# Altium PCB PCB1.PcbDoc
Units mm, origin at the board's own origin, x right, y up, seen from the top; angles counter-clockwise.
Board outline 84.11 x 84.11 mm, 2 copper layers (Top Layer, Bottom Layer); 12 components, 15 nets, 50 pads, 0 vias.
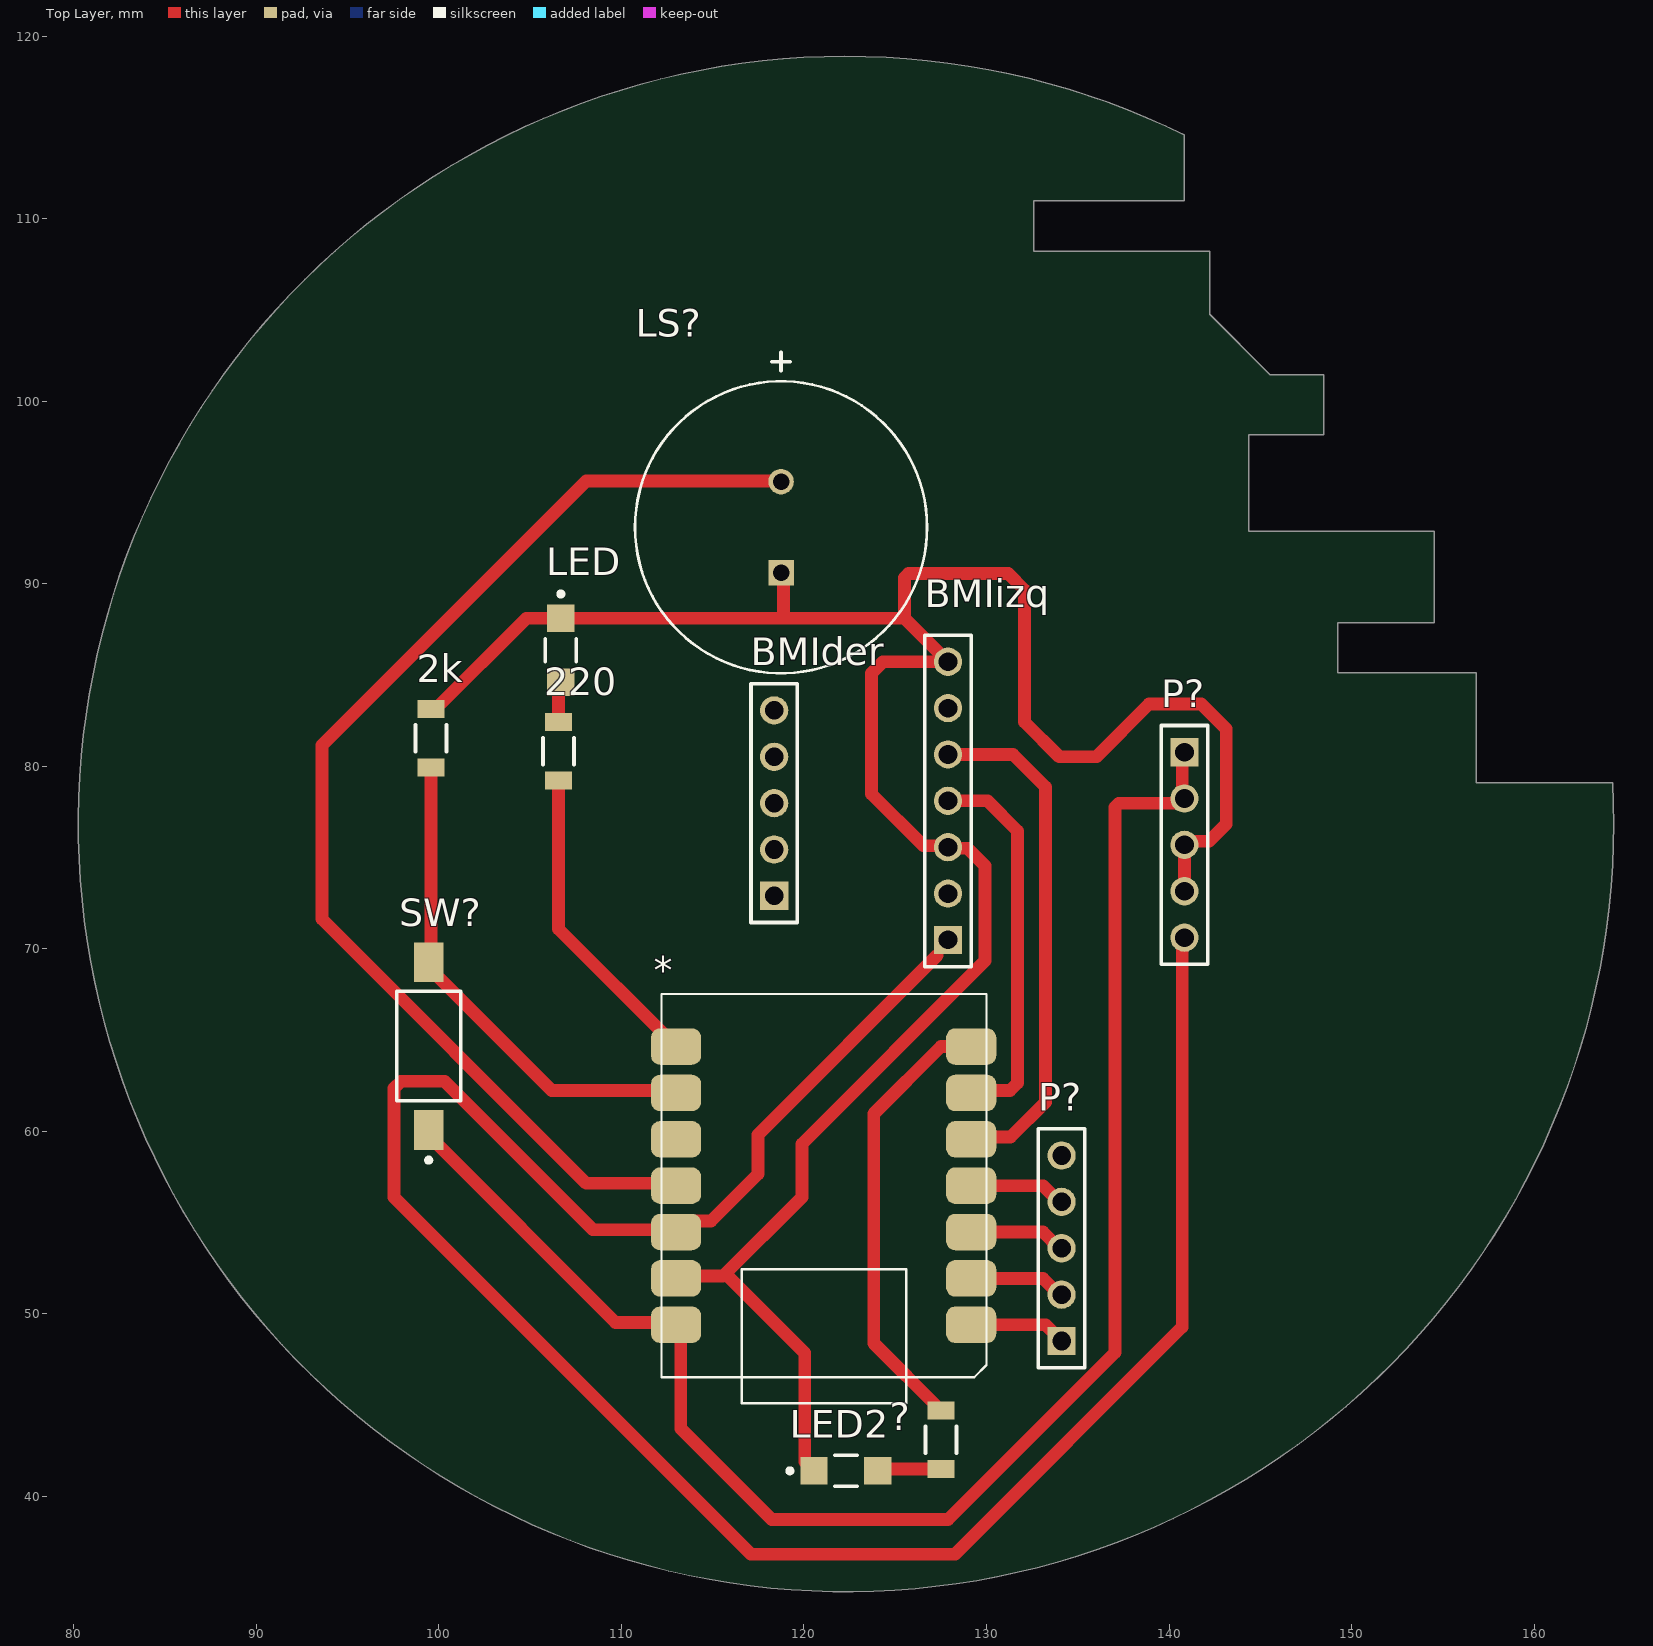
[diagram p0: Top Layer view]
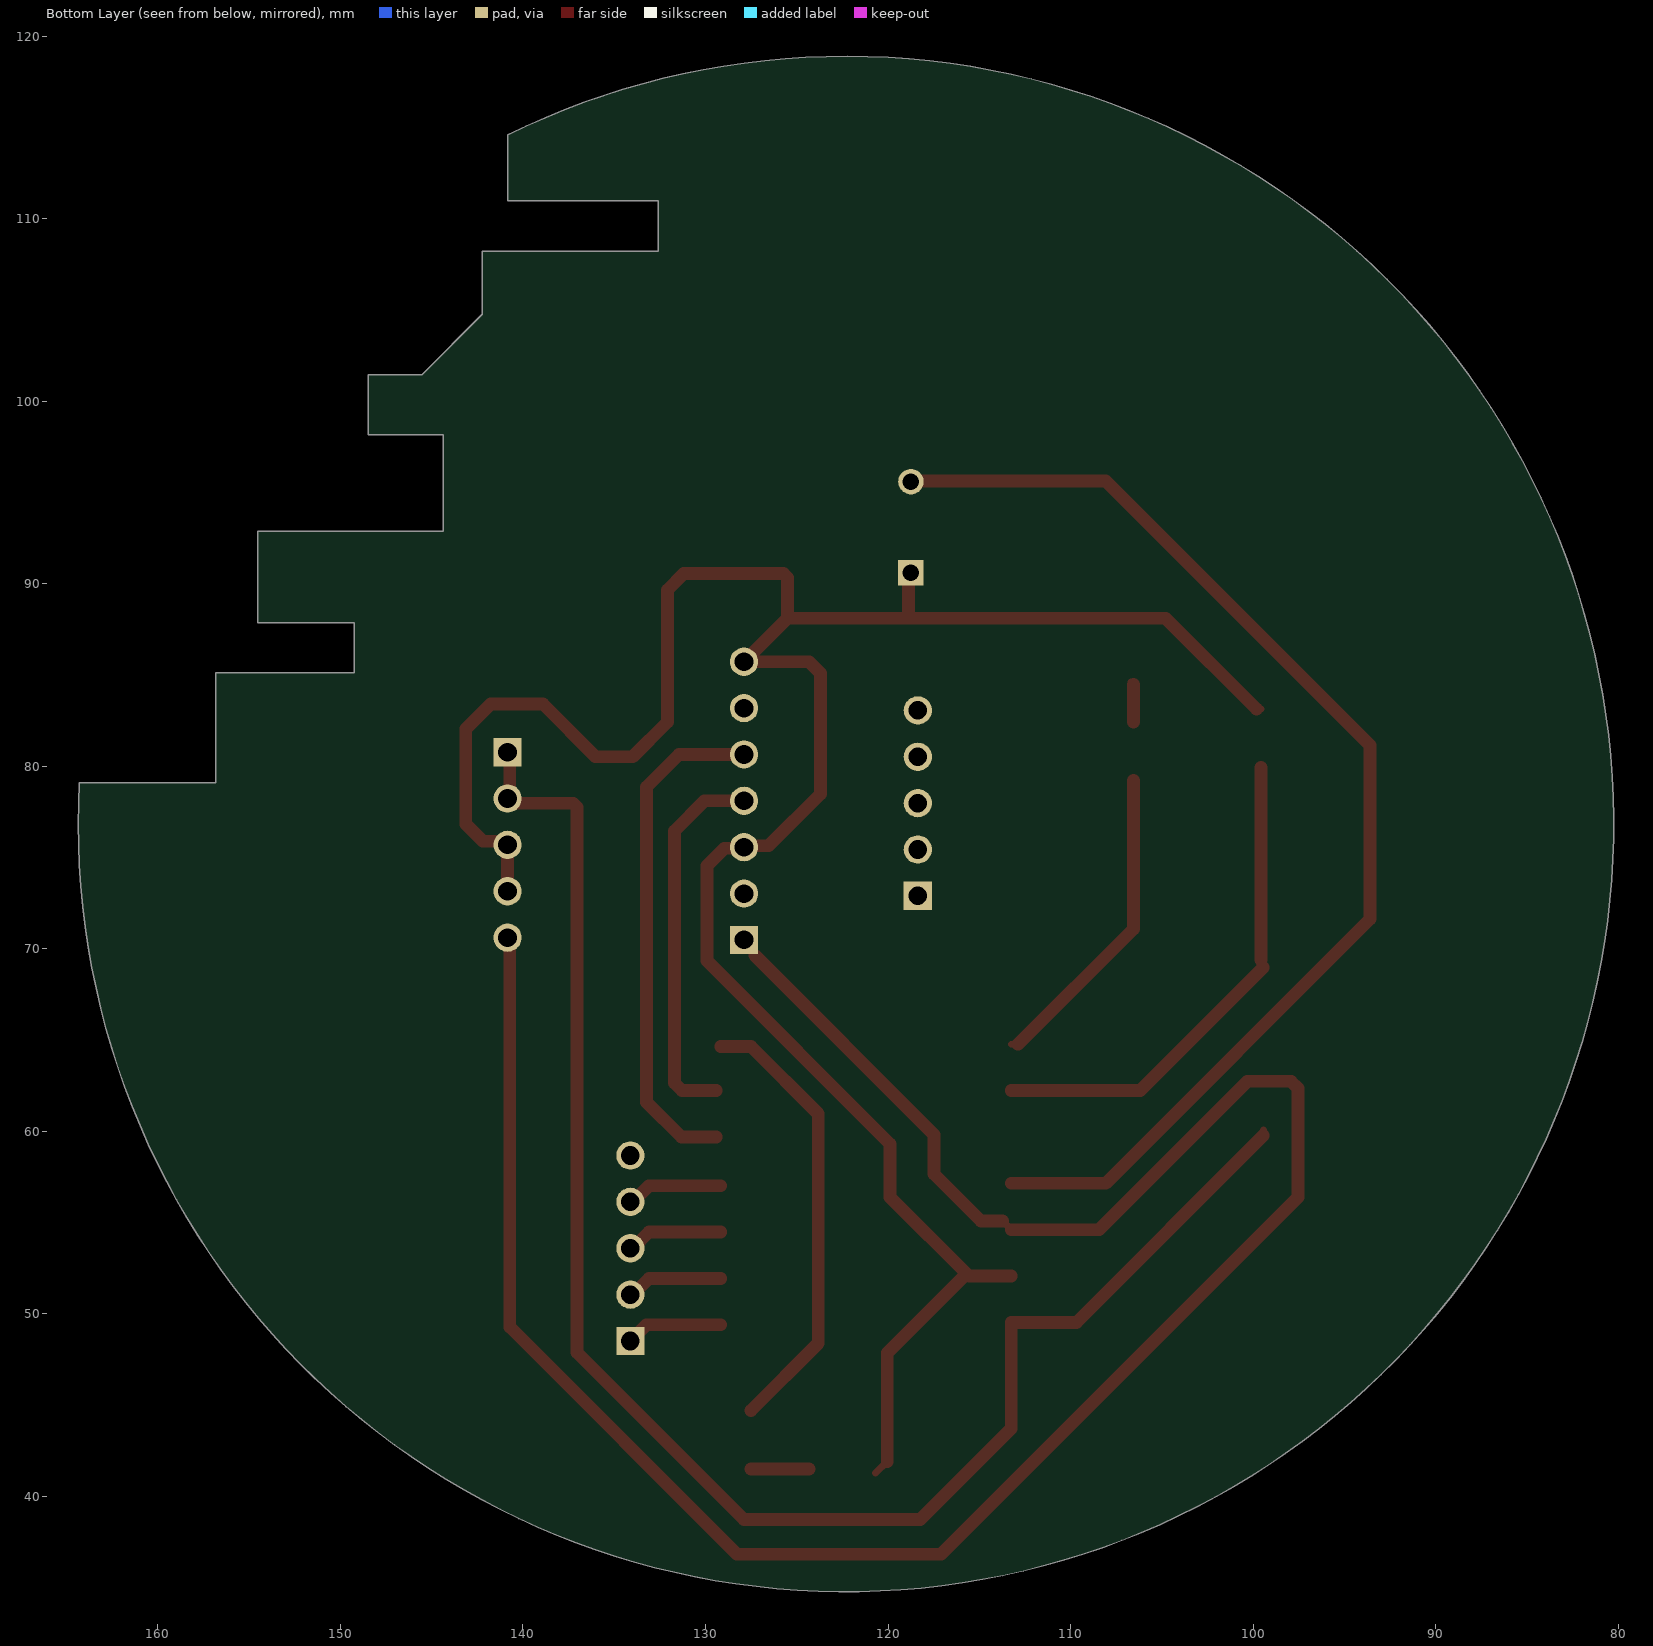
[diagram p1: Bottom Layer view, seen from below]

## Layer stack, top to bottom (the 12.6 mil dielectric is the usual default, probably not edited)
Top Solder: solder mask 0.0102, Solder Resist, Dk 3.5
Top Layer: signal copper 0.0356
Dielectric 1: dielectric 0.32, FR-4, Dk 4.8
Bottom Layer: signal copper 0.0356
Bottom Solder: solder mask 0.0102, Solder Resist, Dk 3.5

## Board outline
144.376,98.148 148.486,98.148 148.486,101.45 145.537,101.45 142.226,104.761 142.226,108.218 132.574,108.218 132.574,110.984 140.829,110.984 140.829,114.59 ccw(c122.301,76.835) 164.296,79.098 156.822,79.098 156.822,85.113 149.248,85.113 149.248,87.861 154.536,87.861 154.536,92.86 144.376,92.86

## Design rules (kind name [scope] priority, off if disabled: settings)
Clearance [All] p1: gap=0.254 ignorepadtopadclearanceinfootprint=FALSE
PolygonConnect [All] p1: connectstyle=Relief reliefconductorwidth=0.254 reliefentries=4 polygonreliefangle="90 Angle" airgapwidth=0.254
RoutingVias [All] p1: holewidth=0.711 width=1.27 viastyle="Through Hole" minholewidth=0.711 minwidth=1.27 maxholewidth=0.711 maxwidth=1.27
SolderMaskExpansion [All] p1: expansion=0.102 istentingtop=FALSE
SupplyNets "Schematic Supply Nets_1" [InNet('GND')] p1: voltage=0.000
SupplyNets "Schematic Supply Nets" [InNet('VCC')] p2: voltage=0.000
Width [OnLayer('Mechanical 1')] p1: maxlimit=0.7 minlimit=0.7 preferedwidth=0.7 minimp=50.000000 maximp=50.000000 favimp=50.000000
30 further rules are at their usual default settings.

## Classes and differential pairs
component class Sheet1: 2k 220 * ? BMIder BMIizq LED LED2 LS? P? SW?

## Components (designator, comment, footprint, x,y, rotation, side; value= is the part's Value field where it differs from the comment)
2k "RC1206JR-070RL" FP-RC1206-MFG 99.568,81.534 r270 top value=0Ω
220 "RC1206JR-070RL" FP-RC1206-MFG 106.553,80.823 r90 top value=0Ω
* "XIAO ESP32C3" MOUDLE14P-SMD-2.54-21X17.8MM 129.994,67.523 r180 top value=MOUDLE-SEEEDUINO-XIAO-ESP32C3
? "RC1206JR-070RL" FP-RC1206-MFG 127.508,43.104 r270 top value=0Ω
BMIder "TSW-105-05-L-S" SMTC-TSW-105-05-X-S 118.364,72.898 r90 top
BMIizq "TSW-107-05-G-S" SMTC-TSW-107-05-X-S 127.889,70.485 r90 top
LED "LTST-C150AKT" FP-LTST-C150AKT-MFG 106.68,86.36 r270 top
LED2 "LTST-C150AKT" FP-LTST-C150AKT-MFG 122.301,41.402 r0 top
LS? "SD1614T5-A1" FP-SD1614T5-A1-MFG 118.745,93.091 r90 top
P? "TSW-105-05-L-S" SMTC-TSW-105-05-X-S 134.112,48.514 r90 top
P? "TSW-105-05-L-S" SMTC-TSW-105-05-X-S 140.843,80.772 r270 top
SW? "FSMSMTR" TECO-FSMSMTR_V 99.441,64.666 r90 top

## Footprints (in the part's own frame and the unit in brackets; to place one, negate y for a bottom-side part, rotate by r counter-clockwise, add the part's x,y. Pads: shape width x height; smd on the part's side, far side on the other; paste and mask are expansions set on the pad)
FP-LTST-C150AKT-MFG [mm]
  rect 1.5x1.5 smd paste+0 mask+0: 1(-1.75,0) 2(1.75,0)
  silkscreen extent -3.2,-0.85 0.63,0.85, body extent -2.6,-0.95 2.6,0.95, height 0.25
FP-RC1206-MFG [mm]
  rect 1x1.5 smd paste+0 mask+0: 1(-1.6,0) 2(1.6,0)
  silkscreen extent -0.72,-0.85 0.72,0.85, body extent -2.2,-0.95 2.2,0.95, height 0.25
FP-SD1614T5-A1-MFG [mm]
  rect 1.4x1.4 hole 0.9 paste-2539.97 mask+0: 1(-2.5,0)
  round 1.4 hole 0.9 paste-2539.97 mask+0: 2(2.5,0)
  silkscreen extent -8,-8 9.57,8, body extent -8.1,-8.1 8.1,8.1, height 0.25
MOUDLE14P-SMD-2.54-21X17.8MM [mm]
  rrect50% 2.75x2 smd: 1(0.835,18.12) 2(0.835,15.58) 3(0.835,13.04) 4(0.835,10.5) 5(0.835,7.96) 6(0.835,5.42) 7(0.835,2.88) 8(17,2.88) 9(17,5.42) 10(17,7.96) 11(17,10.5) 12(17,13.04) 13(17,15.58) 14(17,18.12)
  silkscreen extent 0,0 17.8,22.42, body extent 0,0 17.78,22.46, height 4.19
SMTC-TSW-105-05-X-S [mm] ".025 SQ Post Terminal Strip Assembly, 1x5 Pins, Vertical, 2.54mm Pitch, Male"
  rect 1.55x1.55 hole 1.02: 1(0,0)
  round 1.55 hole 1.02: 2(2.54,0) 3(5.08,0) 4(7.62,0) 5(10.16,0)
  silkscreen extent -1.46,-1.27 11.62,1.27, body extent -1.27,-1.27 11.43,1.27, height 5.21
SMTC-TSW-107-05-X-S [mm] ".025 SQ Post Terminal Strip Assembly, 1x7 Pins, Vertical, 2.54mm Pitch, Male"
  rect 1.55x1.55 hole 1.02: 1(0,0)
  round 1.55 hole 1.02: 2(2.54,0) 3(5.08,0) 4(7.62,0) 5(10.16,0) 6(12.7,0) 7(15.24,0)
  silkscreen extent -1.46,-1.27 16.7,1.27, body extent -1.27,-1.27 16.51,1.27, height 5.21
TECO-FSMSMTR_V [mm] "SMD, 2-Leads, Body 6x3.5mm, Pitch 9.19mm"
  rect 2.2x1.6 smd: 1(-4.595,0)
  rect 2.18x1.6 smd: 2(4.595,0)
  silkscreen extent -6.37,-1.75 3,1.75, body extent -4.98,-1.75 4.98,1.75, height 4.4

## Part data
2k 220 ?: library part CMP-2100-03681-2, "RES SMD 0 OHM JUMPER 1/4W 1206", Manufacturer=YAGEO, Package=RC1206, Power Rating=0.25W, Resistance=0Ω, Temperature="-55°C to +155°C", Temperature Coefficient=300ppm/°C, Temperature Range High=+155°C, Temperature Range Low=-55°C, Tolerance=5%, Voltage Rating=200V
*: library part MOUDLE-SEEEDUINO-XIAO-ESP32C3
BMIder P? P?: library part CMP-1024-00366-1, "0.025\" SQ Post Header, Through-hole, Vertical, -55 to 125 degC, 2.54 mm Pitch, 5-Pin, Male, RoHS", Manufacturer=Samtec, Temperature Range="-55 to 125 degC"
BMIizq: library part CMP-1024-00400-1, "0.025\" SQ Post Header, Through-hole, Vertical, -55 to 125 degC, 2.54 mm Pitch, 7-Pin, Male, RoHS", Manufacturer=Samtec, Temperature Range="-55 to 125 degC"
LED LED2: library part CMP-22017-000004-1, "LED AMBER CLEAR SMD", Colour=Amber, Forward Current=30mA, Forward Voltage=2.1V, Manufacturer=Lite-On, Package=0, Power Dissipation=100mW, Reverse Voltage=5V, Temperature="-55°C to +85°C", Temperature Range High=+85°C, Temperature Range Low=-55°C
LS?: library part CMP-08413-000005-1, "BUZZER MAGNETIC 5V 80DB 2048HZ 1", Frequency=2.048kHz, Max Operating Temperature=85°C, Min Operating Temperature=-40°C, Operating Supply Current=80mA, Voltage Rating=5V
SW?: library part CMP-2000-07501-1, "FSMSM Push Button Switch, 50 mA, -35 to 85 degC, 2-Pin SMD, RoHS, Tape and Reel", Case\/Package=SMD/SMT, Contact Current Rating=50mA, Contact Resistance=100mOhm, Manufacturer="TE Connectivity", Max Operating Temperature=85degC, Max Voltage Rating (DC)=12V, Min Operating Temperature=-35degC, Operating Force=180gf, Package Description="2-Pin Surface Mount Device, Body 6 x 3.5 mm, Pitch 9.19 mm", Package Quantity=1800, Voltage Rating (DC)=24V

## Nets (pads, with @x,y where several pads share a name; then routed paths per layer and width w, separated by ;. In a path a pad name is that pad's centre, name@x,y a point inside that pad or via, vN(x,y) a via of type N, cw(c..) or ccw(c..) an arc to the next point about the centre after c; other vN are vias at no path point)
3v3: *.12 BMIizq.1 P?.5@140.843,70.612 | length 125.4
  Top Layer w0.381: *.12@113.248,54.61 *.12@113.723,55.085 ; 127.305,69.647 127.305,69.901 BMIizq.1
  Top Layer w0.7: *.12@113.248,54.61 108.449,54.61 100.321,62.738 97.917,62.738 97.536,62.357 97.536,56.388 117.094,36.83 128.27,36.83 140.716,49.276 P?.5@140.716,70.358 ; *.12@113.723,55.085 114.902,55.085 117.475,57.658 117.475,59.817 127.305,69.647
boton: 2k.2 *.9 SW?.2 | length 27.6
  Top Layer w0.381: SW?.2@99.441,68.971 SW?.2 SW?.2@99.568,69.388
  Top Layer w0.7: SW?.2@99.441,68.971 106.182,62.23 *.9@113.248,62.23 ; SW?.2@99.568,69.388 2k.2
BUZZER: *.11 LS?.2 | length 66.4
  Top Layer w0.7: *.11@113.248,57.15 108.077,57.15 93.599,71.628 93.599,81.153 108.077,95.631 LS?.2@118.872,95.631
GND: 2k.1 *.13 BMIizq.3 BMIizq.7 LED2.1 LED.1 LS?.1 P?.3@140.843,75.692 P?.4@140.843,73.152 | length 137.1
  Top Layer w0.381: 2k.1 2k.1@99.818,83.134 ; 115.57,52.07 115.824,52.07 ; 118.745,88.11 118.872,88.237 ; LED2.1@120.043,41.91 LED2.1@120.678,41.275 ; BMIizq.3@127.813,75.641 BMIizq.3 BMIizq.3@127.952,75.502 ; P?.3@140.843,75.692 P?.3@141.046,75.895
  Top Layer w0.7: 2k.1@99.818,83.134 104.794,88.11 LED.1 118.745,88.11 125.504,88.11 ; *.13@113.248,52.07 115.57,52.07 119.888,56.388 119.888,59.309 129.921,69.342 129.921,74.549 128.968,75.502 BMIizq.3@127.952,75.502 ; 115.824,52.07 120.043,47.851 LED2.1@120.043,41.91 ; 118.872,88.237 LS?.1@118.872,90.504 ; BMIizq.3@127.813,75.641 126.543,75.641 123.698,78.486 123.698,85.09 124.333,85.725 BMIizq.7 125.504,88.11 ; P?.4@140.843,73.152 P?.3@140.843,75.692 ; P?.3@141.046,75.895 142.189,75.895 143.129,76.835 143.129,82.042 141.763,83.408 138.907,83.408 136.017,80.518 133.985,80.518 132.08,82.423 132.08,89.662 131.191,90.551 125.727,90.551 125.504,90.328 125.504,88.11
LED: 220.1 *.8 | length 17.4
  Top Layer w0.381: *.8@112.873,64.77 *.8@113.248,64.77
  Top Layer w0.7: 220.1 106.553,71.09 *.8@112.873,64.77
LED2: *.7 ?.1 | length 24.6
  Top Layer w0.7: ?.1 123.825,48.387 123.825,60.96 127.508,64.643 *.7
M1: *.1 P?.1@134.112,48.514 | length 5.3
  Top Layer w0.7: *.1 133.223,49.403 P?.1@134.112,48.514
M2: *.2 P?.2@134.112,51.054 | length 5.3
  Top Layer w0.381: P?.2@133.986,51.054 P?.2@134.112,51.054
  Top Layer w0.7: *.2 133.097,51.943 P?.2@133.986,51.054
M3: *.3 P?.3@134.112,53.594 | length 5.3
  Top Layer w0.381: P?.3@133.986,53.594 P?.3@134.112,53.594
  Top Layer w0.7: *.3 133.097,54.483 P?.3@133.986,53.594
M4: *.4 P?.4@134.112,56.134 | length 5.3
  Top Layer w0.381: P?.4@133.986,56.134 P?.4@134.112,56.134
  Top Layer w0.7: *.4 133.097,57.023 P?.4@133.986,56.134
Net220_2: 220.2 LED.2 | length 2.2
  Top Layer w0.381: LED.2@106.553,84.483 LED.2
  Top Layer w0.7: 220.2 LED.2@106.553,84.483
Net?_2: ?.2 LED2.2 | length 3.2
  Top Layer w0.7: LED2.2@124.33,41.504 ?.2
SCL: *.6 BMIizq.4 | length 20.8
  Top Layer w0.7: BMIizq.4 130.048,78.105 131.699,76.454 131.699,62.64 131.289,62.23 *.6@129.413,62.23
SDA: *.5 BMIizq.5 | length 27.9
  Top Layer w0.7: BMIizq.5 131.445,80.645 133.223,78.867 133.223,61.595 131.318,59.69 *.5@129.413,59.69
VCC: *.14 P?.1@140.843,80.772 P?.2@140.843,78.232 SW?.1 | length 90
  Top Layer w0.381: SW?.1@99.441,59.771 SW?.1
  Top Layer w0.7: SW?.1@99.441,59.771 109.682,49.53 113.248,49.53 113.248,43.724 118.237,38.735 127.889,38.735 137.033,47.879 137.033,77.755 137.256,77.978 140.716,77.978 P?.1@140.716,80.518
pads on no net: *.10 BMIder.1 BMIder.2 BMIder.3 BMIder.4 BMIder.5 BMIizq.2 BMIizq.6 P?.5@134.112,58.674

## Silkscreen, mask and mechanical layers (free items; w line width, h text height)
Mechanical 1:
  lines w2: 80.483,73.187 83.108,75.812 83.108,77.717 80.695,80.13 ; 163.172,79.098 161.671,77.597 161.671,75.692 164.084,73.279 ; 132.574,108.218 142.226,108.218 142.226,104.761 145.537,101.45 148.486,101.45 148.486,98.148 144.376,98.148 144.376,92.86 154.536,92.86 154.536,87.861 149.248,87.861 149.248,85.113 156.822,85.113 156.822,79.098 164.296,79.098 cw(c122.301,76.835) 140.829,114.59 140.829,110.984 132.574,110.984 132.574,108.218
Mechanical 2:
  lines w0.7: 143.129,63.5 161.671,63.5
  lines w1: 82.169,88.392 98.298,88.392 ; 85.598,96.393 91.44,96.393 91.44,88.392 ; 85.852,74.93 85.852,67.818 92.456,67.818 ; 89.281,51.562 96.52,51.562 ; 89.281,102.997 100.076,102.997 ; 89.535,56.007 89.535,62.103 ; 90.17,75.311 90.17,77.597 ; 91.186,96.52 97.028,96.52 ; 91.313,68.199 91.313,74.93 ; 91.694,105.537 141.986,105.537 ; 91.821,75.184 84.074,75.184 84.074,77.597 91.948,77.597 ; 94.107,55.88 94.107,66.675 ; 94.117,55.759 ccw(c133.477,77.275) 106.888,41.148 ; 94.488,84.963 94.488,88.138 ; 95.631,77.597 97.663,77.597 ; 95.758,75.184 97.663,75.184 ; 97.536,94.107 100.584,94.107 ; 97.536,97.79 97.663,97.79 99.06,96.393 100.33,96.393 ; 98.425,100.584 98.552,100.584 100.584,98.552 ; 99.695,102.362 99.949,102.362 101.727,100.584 102.108,100.584 105.41,97.282 ; 99.817,89.764 cw(c106.553,96.139) 115.744,97.381 ; 100.33,97.155 100.457,97.155 ; 100.457,96.52 105.41,96.52 ; 101.956,91.936 cw(c106.553,96.139) 112.421,98.226 ; 101.981,41.148 108.458,41.148 ; 101.981,75.311 104.902,75.311 ; 101.981,91.948 105.41,95.377 ; 102.108,77.597 104.394,77.597 ; 102.362,45.085 102.362,49.657 ; 102.489,104.394 104.521,102.362 ; 102.809,105.924 cw(c115.762,104.601) 106.941,114.178 ; 103.124,77.851 103.124,83.82 ; 103.759,114.427 140.081,114.427 ; 104.521,69.088 104.521,75.057 ; 105.559,95.464 cw(c106.934,96.266) 108.221,97.202 ; 106.045,97.536 106.045,102.362 ; 106.172,64.643 110.363,64.643 ; 106.553,102.489 106.553,105.41 ; 106.934,90.932 106.934,92.202 ; 107.188,97.917 107.188,98.552 109.982,101.346 ; 107.696,97.663 112.396,97.663 ; 108.077,75.438 113.157,75.438 ; 108.204,77.724 113.411,77.724 ; 108.585,101.981 108.585,105.029 108.712,105.156 ; 108.839,93.472 109.728,92.583 ; 109.855,91.186 109.855,92.456 ; 109.871,47.554 ccw(c140.088,62.512) 111.379,44.831 ; 110.363,101.346 110.363,101.473 112.268,103.378 ; 110.49,75.692 110.49,77.724 ; 110.744,70.739 110.744,72.771 ; 111.379,91.948 113.157,90.17 ; 112.014,99.187 112.903,99.187 114.427,100.711 ; 112.141,105.664 cw(c131.861,104.571) 114.606,114.181 ; 112.649,94.615 114.935,92.329 ; 112.649,97.409 113.538,97.409 115.316,99.187 ; 113.157,89.789 ccw(c106.691,96.255) 115.547,93.978 ; 115.062,105.918 cw(c134.782,104.825) 117.527,114.435 ; 115.824,70.231 122.682,70.231 ; 120.396,86.868 121.539,85.725 121.539,76.454 121.539,74.803 122.682,74.803 ; 121.666,44.069 121.666,57.912 ; 122.682,68.961 122.682,74.739 ; 123.444,105.41 123.444,102.235 127.635,102.235 131.572,102.235 ; 124.46,114.427 124.46,112.268 127.254,112.268 127.254,114.427 ; 125.857,105.664 125.857,112.268 ; 126.238,47.752 126.238,55.753 ; 127.762,102.362 127.762,105.537 ; 128.524,97.282 144.272,97.409 ; 129.603,97.599 129.603,102.235 ; 130.429,82.169 130.429,89.027 ; 131.572,105.537 131.572,102.235 ; 134.62,75.438 134.62,77.47 ; 134.874,82.804 134.874,89.154 138.557,89.154 ; 135.255,63.627 135.255,66.802 ; 135.382,70.485 135.382,72.517 ; 136.159,41.311 ccw(c116.141,70.421) 148.198,55.572 ; 138.684,86.233 138.684,90.932 ; 138.684,87.884 144.018,87.884 ; 138.811,58.547 138.811,63.373 ; 138.811,90.17 144.018,90.17 144.018,87.884 ; 142.621,55.88 158.369,55.88 ; 143.446,63.5 143.446,68.008 145.225,68.008 145.225,63.817 ; 144.145,102.235 131.572,102.235 ; 144.907,75.184 151.384,75.184 ; 144.97,84.391 145.351,84.391 145.415,84.455 145.415,75.184 ; 145.161,77.597 160.274,77.597 ; 145.542,84.074 144.272,84.074 144.272,87.884 144.018,87.884 ; 149.352,77.597 149.352,81.534 ; 151.13,55.88 151.13,63.373 ; 151.384,77.597 151.384,75.184 ; 153.67,75.184 153.67,67.31 154.051,66.929 157.861,66.929 ; 160.274,75.184 151.384,75.184 ; 162.941,66.929 157.861,66.929 ; 163.195,70.866 157.861,70.866 157.861,66.929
